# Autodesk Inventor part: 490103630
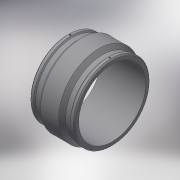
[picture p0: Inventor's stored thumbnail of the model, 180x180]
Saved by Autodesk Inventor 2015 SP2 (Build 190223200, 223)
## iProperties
Created: 2017-06
Part Number: 490103630
Material: Generic
Description: PLASSON COUPLER 630
Document SubType Name: Modeling
Designer: KIM
Mass: 43579.7 g
Surface Area: 20126.5 cm^2
Volume: 43579.7 cm^3
Density: 1 g/cm^3
Appearance: Default
Author: KIM
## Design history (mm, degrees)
derived "490103.ipt"
feature "Solid1::490103.ipt"
tag "TaggingFeature1"
body "Solid1"
other parameters: "d13" = 418, "d15" = 209, "d16" = 209, "d22" = 712, "d23" = 759, "d24" = 690.64, "d25" = 135 deg, "d26" = 167.2, "d27" = 135 deg, "d29" = 356, "d35" = 15, "d39" = 0, "d40" = 4, "d41" = 14, "d42" = 0, "d43" = 135 deg, "d44" = 45.98, "d46" = 6, "d47" = 0, "L_" = 418, "L_1" = 209, "D_" = 759, "A_" = 356, "d_2" = 12
